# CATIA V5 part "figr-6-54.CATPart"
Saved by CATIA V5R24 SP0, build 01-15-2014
Part number: Part1
Bounding box of the stored display mesh (mm): x -46.66 to 43.071, y -43.071 to 47.059, z 0 to 20
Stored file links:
  D:\KAVITA\CATIA V5-6R2014 Project_ Kavita\CATIA V5-6R2014_partfiles\Partfiles\c06_catia_v5-6r2014_prt\figr-6-54.CATPart
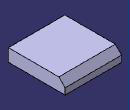
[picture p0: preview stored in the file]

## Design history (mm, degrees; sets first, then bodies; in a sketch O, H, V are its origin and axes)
Body1 (main body)
  Sketch1 on xy-plane, origin (0, 0, 0), H (1, 0, 0), V (0, 1, 0)
    line L1 (-46.6598, 47.0586) -> (43.0706, 47.0586)
    line L2 (43.0706, 47.0586) -> (43.0706, -43.0706)
    line L3 (43.0706, -43.0706) -> (-46.6598, -43.0706)
    line L4 (-46.6598, -43.0706) -> (-46.6598, 47.0586)
    horizontal: L1 H, L3 H
    vertical: L2 V, L4 V
  Pad1: profile Sketch1, direction (0, 0, 1), length 20
  Chamfer1: length 10, angle 45, on edge [face of Pad1 | face of Pad1]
